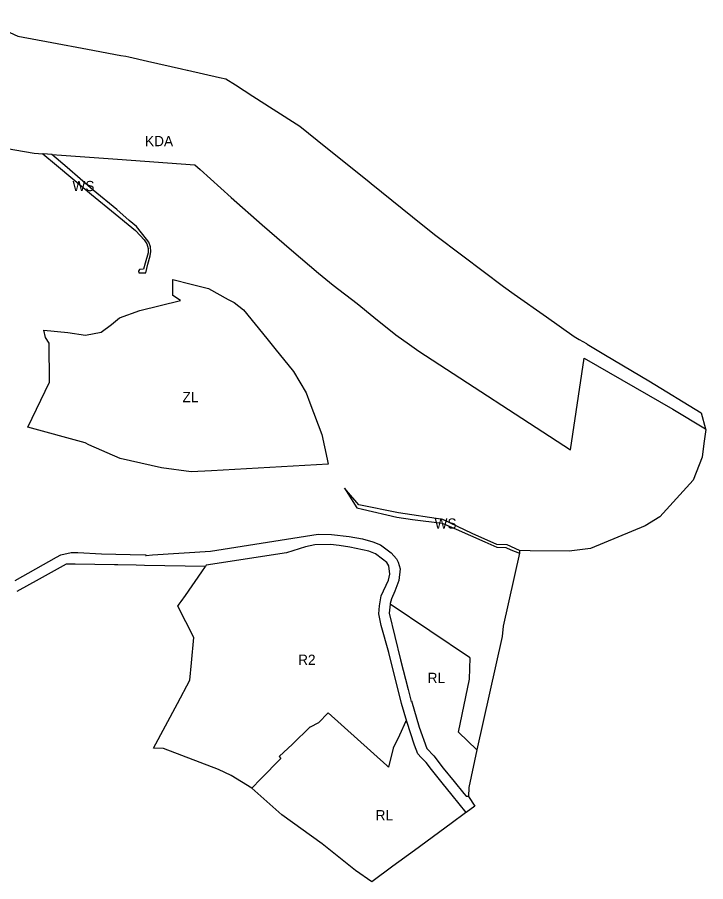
# Model space of a CAD drawing. Extents: x 7413438 to 7416393, y 5541665 to 5544118.
# Drawn here: x 7415988 to 7416393, y 5542838 to 5543346 of the extents above; entities that cross this region are included whole.
import ezdxf

# ---------------------------------------------------------------- set-up
doc = ezdxf.new("R2010")
doc.units = 0
doc.layers.add('linie_rozgraniczajace', color=7, linetype='Continuous')
doc.layers.add('oznaczenia_przeznaczen', color=7, linetype='Continuous')

msp = doc.modelspace()

# ---------------------------------------------------------------- linework, layer by layer
at = {"layer": 'linie_rozgraniczajace'}
for p, q in [((7415964.26, 5543346), (7415988.61, 5543334.9)), ((7415988.61, 5543334.9), (7416008.67, 5543331.16)), ((7416008.67, 5543331.16), (7416029.55, 5543327.27)), ((7416029.55, 5543327.27), (7416049.05, 5543323.64)), ((7416049.05, 5543323.64), (7416052.1, 5543323.07)), ((7416052.1, 5543323.07), (7416053.82, 5543322.68)), ((7416053.82, 5543322.68), (7416064.8, 5543320.22)), ((7416064.8, 5543320.22), (7416084.77, 5543315.73)), ((7416084.77, 5543315.73), (7416088.21, 5543314.96)), ((7416088.21, 5543314.96), (7416088.33, 5543314.93)), ((7416088.33, 5543314.93), (7416107.21, 5543310.69)), ((7416107.21, 5543310.69), (7416110.82, 5543309.87)), ((7416110.82, 5543309.87), (7416116.51, 5543306.22)), ((7416116.51, 5543306.22), (7416126.74, 5543299.66)), ((7416126.74, 5543299.66), (7416138.7, 5543291.99)), ((7416138.7, 5543291.99), (7416154.38, 5543281.93)), ((7416154.38, 5543281.93), (7416169.6, 5543269.75)), ((7415958.11, 5543273.01), (7415998.1, 5543266.23)), ((7415998.1, 5543266.23), (7416003.27, 5543265.76)), ((7416003.27, 5543265.76), (7416011.26, 5543259.11)), ((7416003.53, 5543265.74), (7416003.27, 5543265.76)), ((7416008.6, 5543265.34), (7416003.53, 5543265.74)), ((7416008.6, 5543265.34), (7416014.24, 5543264.89)), ((7416017.58, 5543257.77), (7416008.6, 5543265.34)), ((7416014.24, 5543264.89), (7416047.21, 5543262.67)), ((7416169.6, 5543269.75), (7416194.01, 5543250.2)), ((7416047.21, 5543262.67), (7416092.62, 5543259.25)), ((7416011.26, 5543259.11), (7416020.83, 5543251.16)), ((7416032.85, 5543244.48), (7416017.58, 5543257.77)), ((7416092.62, 5543259.25), (7416095.86, 5543256.53)), ((7416095.86, 5543256.53), (7416114.03, 5543240.05)), ((7416020.83, 5543251.16), (7416031.97, 5543241.8)), ((7416194.01, 5543250.2), (7416196.24, 5543248.41)), ((7416196.24, 5543248.41), (7416220.56, 5543228.8)), ((7416031.97, 5543241.8), (7416045.82, 5543230.57)), ((7416046.75, 5543233.11), (7416032.85, 5543244.48)), ((7416114.03, 5543240.05), (7416132.19, 5543223.99)), ((7416045.82, 5543230.57), (7416055.66, 5543222.46)), ((7416054.06, 5543226.67), (7416046.75, 5543233.11)), ((7416058.31, 5543223.08), (7416054.06, 5543226.67)), ((7416220.56, 5543228.8), (7416233.46, 5543218.41)), ((7416055.66, 5543222.46), (7416057.67, 5543220.64)), ((7416057.67, 5543220.64), (7416060.43, 5543217.77)), ((7416064.15, 5543215.54), (7416058.31, 5543223.08)), ((7416132.19, 5543223.99), (7416149.45, 5543209.17)), ((7416060.43, 5543217.77), (7416062.78, 5543215.14)), ((7416062.78, 5543215.14), (7416064.38, 5543212.96)), ((7416065.51, 5543213.87), (7416064.15, 5543215.54)), ((7416233.46, 5543218.41), (7416250.23, 5543205.76)), ((7416064.38, 5543212.96), (7416065.23, 5543210.14)), ((7416065.23, 5543210.14), (7416065.16, 5543207.67)), ((7416066.66, 5543211.1), (7416065.51, 5543213.87)), ((7416066.73, 5543208.38), (7416066.66, 5543211.1)), ((7416149.45, 5543209.17), (7416165.37, 5543195.73)), ((7416065.16, 5543207.67), (7416063.37, 5543201.55)), ((7416064.91, 5543201.01), (7416066.31, 5543205.82)), ((7416066.31, 5543205.82), (7416066.73, 5543208.38)), ((7416250.23, 5543205.76), (7416274.14, 5543187.71)), ((7416063.37, 5543201.55), (7416062.47, 5543197.96)), ((7416063.74, 5543195.84), (7416064.91, 5543201.01)), ((7416060.12, 5543197.87), (7416059.58, 5543196.76)), ((7416059.58, 5543196.76), (7416059.75, 5543195.91)), ((7416059.75, 5543195.91), (7416063.74, 5543195.84)), ((7416062.47, 5543197.96), (7416060.12, 5543197.87)), ((7416165.37, 5543195.73), (7416173.92, 5543188.53)), ((7416079.65, 5543182.59), (7416079.61, 5543191.89)), ((7416079.61, 5543191.89), (7416090.46, 5543189.16)), ((7416090.46, 5543189.16), (7416100.7, 5543186.6)), ((7416100.7, 5543186.6), (7416112.31, 5543180.21)), ((7416173.92, 5543188.53), (7416188.02, 5543177.72)), ((7416274.14, 5543187.71), (7416280.35, 5543183.33)), ((7416060.21, 5543173.64), (7416084.18, 5543179.62)), ((7416084.18, 5543179.62), (7416079.65, 5543182.59)), ((7416112.31, 5543180.21), (7416115.74, 5543178.32)), ((7416280.35, 5543183.33), (7416299.31, 5543169.98)), ((7416048.42, 5543169.44), (7416060.21, 5543173.64)), ((7416115.74, 5543178.32), (7416121.24, 5543174.19)), ((7416121.24, 5543174.19), (7416134.9, 5543157.31)), ((7416188.02, 5543177.72), (7416197.88, 5543169.72)), ((7416043.64, 5543165.38), (7416048.42, 5543169.44)), ((7416197.88, 5543169.72), (7416210.82, 5543159.43)), ((7416299.31, 5543169.98), (7416315.66, 5543158.46)), ((7416037.64, 5543160.91), (7416043.64, 5543165.38)), ((7416004.9, 5543157.83), (7416003.95, 5543162.06)), ((7416003.95, 5543162.06), (7416018.07, 5543160.8)), ((7416018.07, 5543160.8), (7416028.33, 5543159.29)), ((7416028.33, 5543159.29), (7416037.64, 5543160.91)), ((7416210.82, 5543159.43), (7416218.75, 5543153.63)), ((7416315.66, 5543158.46), (7416318.55, 5543156.74)), ((7416007.07, 5543154.49), (7416004.9, 5543157.83)), ((7416007.2, 5543131.63), (7416007.07, 5543154.49)), ((7416134.9, 5543157.31), (7416139.71, 5543151.36)), ((7416218.75, 5543153.63), (7416224.31, 5543149.72)), ((7416318.55, 5543156.74), (7416322.76, 5543154.23)), ((7416322.76, 5543154.23), (7416323.21, 5543153.96)), ((7416323.21, 5543153.96), (7416334.03, 5543147.49)), ((7416139.71, 5543151.36), (7416150.57, 5543137.93)), ((7416224.31, 5543149.72), (7416313.49, 5543091.85)), ((7416313.49, 5543091.85), (7416321.55, 5543145.7)), ((7416321.55, 5543145.7), (7416373.58, 5543115.7)), ((7416334.03, 5543147.49), (7416359.44, 5543132.32)), ((7416150.57, 5543137.93), (7416157.98, 5543125.35)), ((7415994.55, 5543105.07), (7416007.2, 5543131.63)), ((7416359.44, 5543132.32), (7416390.16, 5543113.61)), ((7416157.98, 5543125.35), (7416160.18, 5543119.5)), ((7416160.18, 5543119.5), (7416167.19, 5543100.83)), ((7416373.58, 5543115.7), (7416392.82, 5543104.09)), ((7416390.16, 5543113.61), (7416392.82, 5543104.09)), ((7416028.1, 5543095.85), (7415994.55, 5543105.07)), ((7416392.9, 5543103.82), (7416391.85, 5543095.5)), ((7416392.82, 5543104.09), (7416392.9, 5543103.82)), ((7416167.19, 5543100.83), (7416170.37, 5543086.25)), ((7416030.39, 5543094.83), (7416028.1, 5543095.85)), ((7416048.66, 5543086.72), (7416030.39, 5543094.83)), ((7416391.85, 5543095.5), (7416390.84, 5543087.45)), ((7416391.85, 5543095.5), (7416391.85, 5543095.5)), ((7416390.84, 5543087.45), (7416385.47, 5543073.91)), ((7416073.06, 5543081.27), (7416048.66, 5543086.72)), ((7416170.99, 5543083.32), (7416102.34, 5543079.47)), ((7416170.37, 5543086.25), (7416170.99, 5543083.32)), ((7416090.4, 5543078.81), (7416073.06, 5543081.27)), ((7416102.34, 5543079.47), (7416090.4, 5543078.81)), ((7416385.47, 5543073.91), (7416365.99, 5543052.55)), ((7416189.02, 5543059.53), (7416180.6, 5543069.36)), ((7416180.6, 5543069.36), (7416187.89, 5543057.81)), ((7416187.89, 5543057.81), (7416191.2, 5543057.01)), ((7416212.3, 5543054.85), (7416189.02, 5543059.53)), ((7416191.2, 5543057.01), (7416211.33, 5543052.34)), ((7416211.33, 5543052.34), (7416220.55, 5543050.97)), ((7416238.42, 5543050.83), (7416212.3, 5543054.85)), ((7416365.99, 5543052.55), (7416357.3, 5543047.16)), ((7416220.55, 5543050.97), (7416238.04, 5543048.81)), ((7416238.04, 5543048.81), (7416246.14, 5543045.19)), ((7416255.62, 5543042.63), (7416238.42, 5543050.83)), ((7416357.3, 5543047.16), (7416325.24, 5543033.84)), ((7416101.84, 5543032.35), (7416165.08, 5543042.24)), ((7416165.08, 5543042.24), (7416172.95, 5543042.1)), ((7416172.95, 5543042.1), (7416183.33, 5543040.89)), ((7416246.14, 5543045.19), (7416262.98, 5543037.71)), ((7416270.06, 5543036.19), (7416255.62, 5543042.63)), ((7416183.33, 5543040.89), (7416191.18, 5543039.44)), ((7416191.18, 5543039.44), (7416197.24, 5543037.7)), ((7416197.24, 5543037.7), (7416201.74, 5543036.04)), ((7416262.98, 5543037.71), (7416270.19, 5543034.66)), ((7416013.81, 5543030.15), (7416019.99, 5543031.53)), ((7416019.99, 5543031.53), (7416023.91, 5543031.45)), ((7416023.91, 5543031.45), (7416037.78, 5543030.79)), ((7416067.72, 5543030.04), (7416101.8, 5543032.34)), ((7416146.52, 5543031.29), (7416099.2, 5543023.98)), ((7416101.8, 5543032.34), (7416101.84, 5543032.34)), ((7416101.84, 5543032.34), (7416101.84, 5543032.35)), ((7416157.7, 5543034.78), (7416146.52, 5543031.29)), ((7416163.25, 5543036.01), (7416157.7, 5543034.78)), ((7416172.39, 5543036.12), (7416163.25, 5543036.01)), ((7416177.47, 5543035.53), (7416172.39, 5543036.12)), ((7416183.81, 5543034.7), (7416177.47, 5543035.53)), ((7416194.81, 5543032.2), (7416183.81, 5543034.7)), ((7416198.73, 5543030.81), (7416194.81, 5543032.2)), ((7416201.74, 5543036.04), (7416207.97, 5543031.27)), ((7416207.97, 5543031.27), (7416211.08, 5543027.84)), ((7416276.22, 5543036.04), (7416270.06, 5543036.19)), ((7416270.19, 5543034.66), (7416275.42, 5543034.47)), ((7416275.42, 5543034.47), (7416278.42, 5543033.05)), ((7416283.54, 5543032.6), (7416276.22, 5543036.04)), ((7416278.42, 5543033.05), (7416283.36, 5543031.15)), ((7416283.41, 5543032.61), (7416283.36, 5543031.15)), ((7416283.54, 5543032.6), (7416283.41, 5543032.61)), ((7416289.72, 5543032.52), (7416283.54, 5543032.6)), ((7416312.67, 5543032.21), (7416289.72, 5543032.52)), ((7416325.24, 5543033.84), (7416312.67, 5543032.21)), ((7415986.94, 5543015.08), (7416011.39, 5543028.84)), ((7416011.39, 5543028.84), (7416013.81, 5543030.15)), ((7416037.78, 5543030.79), (7416054.7, 5543030.34)), ((7416054.7, 5543030.34), (7416063.67, 5543030.22)), ((7416063.67, 5543030.22), (7416063.77, 5543030.13)), ((7416063.77, 5543030.13), (7416063.73, 5543029.78)), ((7416063.73, 5543029.78), (7416063.99, 5543029.79)), ((7416063.99, 5543029.79), (7416067.72, 5543030.04)), ((7416202.98, 5543027.54), (7416198.73, 5543030.81)), ((7416205.39, 5543025.68), (7416202.98, 5543027.54)), ((7416211.08, 5543027.84), (7416212.2, 5543025.74)), ((7416283.36, 5543031.12), (7416273.83, 5542988.21)), ((7416283.36, 5543031.15), (7416283.36, 5543031.12)), ((7416016.95, 5543024.73), (7416001.1, 5543015.87)), ((7416022.19, 5543024.64), (7416016.95, 5543024.73)), ((7416022.26, 5543024.63), (7416022.19, 5543024.64)), ((7416045.42, 5543024.2), (7416022.26, 5543024.63)), ((7416047.33, 5543024.16), (7416045.42, 5543024.2)), ((7416058.15, 5543023.96), (7416047.33, 5543024.16)), ((7416063.04, 5543023.87), (7416058.15, 5543023.96)), ((7416063.07, 5543023.86), (7416063.04, 5543023.87)), ((7416098.95, 5543023.19), (7416063.07, 5543023.86)), ((7416096.82, 5543020.16), (7416098.95, 5543023.19)), ((7416099.2, 5543023.98), (7416098.95, 5543023.19)), ((7416206.56, 5543023.66), (7416205.39, 5543025.68)), ((7416207.25, 5543018.8), (7416206.56, 5543023.66)), ((7416212.2, 5543025.74), (7416213.25, 5543021.86)), ((7416213.25, 5543021.86), (7416212.51, 5543015.07)), ((7416087.05, 5543006.28), (7416096.82, 5543020.16)), ((7416206.37, 5543015.24), (7416207.25, 5543018.8)), ((7416001.1, 5543015.87), (7415987.94, 5543008.51)), ((7416202.24, 5543005.95), (7416206.37, 5543015.24)), ((7416212.51, 5543015.07), (7416210.2, 5543008.74)), ((7416084.56, 5543002.73), (7416087.05, 5543006.28)), ((7416201.17, 5543000.17), (7416202.24, 5543005.95)), ((7416210.2, 5543008.74), (7416208.12, 5543004.33)), ((7416082.66, 5543000.03), (7416083.43, 5543001.12)), ((7416083.43, 5543001.12), (7416084.56, 5543002.73)), ((7416207.51, 5543001.1), (7416206.81, 5542995.83)), ((7416207.49, 5543001.54), (7416207.44, 5543001.14)), ((7416207.44, 5543001.14), (7416207.51, 5543001.1)), ((7416208.12, 5543004.33), (7416207.49, 5543001.54)), ((7416254.1, 5542969.87), (7416207.51, 5543001.1)), ((7416091.97, 5542981.46), (7416082.66, 5543000.03)), ((7416200.77, 5542995.43), (7416201.17, 5543000.17)), ((7416206.81, 5542995.83), (7416213.57, 5542968.44)), ((7416202.2, 5542988.61), (7416200.77, 5542995.43)), ((7416206.59, 5542972.7), (7416202.2, 5542988.61)), ((7416273.83, 5542988.21), (7416273.19, 5542982.19)), ((7416090.61, 5542966.74), (7416091.97, 5542981.46)), ((7416273.19, 5542982.19), (7416258.46, 5542915.55)), ((7416214.09, 5542942.84), (7416206.59, 5542972.7)), ((7416089.66, 5542956.4), (7416090.61, 5542966.74)), ((7416213.57, 5542968.44), (7416218.01, 5542950.98)), ((7416253.99, 5542956.98), (7416254.54, 5542969.58)), ((7416254.54, 5542969.58), (7416254.1, 5542969.87)), ((7416082.35, 5542942.72), (7416089.66, 5542956.4)), ((7416247.57, 5542926), (7416253.99, 5542956.98)), ((7416218.01, 5542950.98), (7416219.78, 5542943.95)), ((7416068.33, 5542916.52), (7416082.35, 5542942.72)), ((7416217.25, 5542932.13), (7416214.09, 5542942.84)), ((7416219.78, 5542943.95), (7416219.9, 5542944.34)), ((7416219.9, 5542944.34), (7416224.48, 5542928.84)), ((7416170.94, 5542937.32), (7416165.33, 5542931.38)), ((7416205.45, 5542906.24), (7416170.94, 5542937.32)), ((7416165.3, 5542931.4), (7416160.37, 5542928.88)), ((7416165.33, 5542931.38), (7416165.3, 5542931.4)), ((7416216.71, 5542932.4), (7416212.96, 5542924.07)), ((7416216.93, 5542931.58), (7416216.71, 5542932.4)), ((7416217.25, 5542932.13), (7416216.93, 5542931.58)), ((7416221.68, 5542918.32), (7416217.25, 5542932.13)), ((7416157.78, 5542926.48), (7416152.52, 5542921.35)), ((7416160.31, 5542928.92), (7416157.78, 5542926.48)), ((7416160.37, 5542928.88), (7416160.31, 5542928.92)), ((7416224.48, 5542928.84), (7416228.95, 5542916.24)), ((7416258.46, 5542915.55), (7416247.57, 5542926)), ((7416152.52, 5542921.35), (7416149.95, 5542918.92)), ((7416212.96, 5542924.07), (7416209.29, 5542916.5)), ((7416074.22, 5542916.33), (7416068.33, 5542916.52)), ((7416106.58, 5542904), (7416074.22, 5542916.33)), ((7416149.95, 5542918.92), (7416142.14, 5542911.53)), ((7416209.29, 5542916.5), (7416206.52, 5542905.27)), ((7416223.75, 5542913.13), (7416221.68, 5542918.32)), ((7416228.95, 5542916.24), (7416233.19, 5542911.93)), ((7416258.46, 5542915.55), (7416253.59, 5542893.49)), ((7416143.09, 5542910.4), (7416131.51, 5542898.54)), ((7416142.14, 5542911.53), (7416143.09, 5542910.4)), ((7416225.72, 5542910.98), (7416223.75, 5542913.13)), ((7416228.53, 5542908.14), (7416225.72, 5542910.98)), ((7416233.19, 5542911.93), (7416238.66, 5542904.74)), ((7416206.52, 5542905.27), (7416205.45, 5542906.24)), ((7416231.68, 5542904.01), (7416228.53, 5542908.14)), ((7416238.66, 5542904.74), (7416245.08, 5542896.97)), ((7416114.02, 5542900.41), (7416106.58, 5542904)), ((7416126.09, 5542892.99), (7416114.02, 5542900.41)), ((7416237.99, 5542896.13), (7416231.68, 5542904.01)), ((7416131.51, 5542898.54), (7416126.09, 5542892.99)), ((7416243.82, 5542888.87), (7416237.99, 5542896.13)), ((7416245.08, 5542896.97), (7416250.77, 5542889.88)), ((7416143.8, 5542877.44), (7416126.09, 5542892.99)), ((7416250.77, 5542889.88), (7416252.01, 5542888.33)), ((7416253.59, 5542893.49), (7416253.4, 5542888.21)), ((7416252.03, 5542878.67), (7416243.82, 5542888.87)), ((7416252.01, 5542888.33), (7416253.36, 5542888.22)), ((7416253.36, 5542888.22), (7416253.4, 5542888.21)), ((7416253.4, 5542888.21), (7416253.39, 5542888.14)), ((7416253.39, 5542888.14), (7416257.26, 5542882.51)), ((7416257.26, 5542882.51), (7416252.03, 5542878.67)), ((7416167.52, 5542860.29), (7416143.8, 5542877.44)), ((7416251.76, 5542878.47), (7416243.29, 5542872.25)), ((7416252.03, 5542878.67), (7416251.76, 5542878.47)), ((7416243.29, 5542872.25), (7416221.68, 5542856.4)), ((7416187, 5542844.56), (7416167.52, 5542860.29)), ((7416221.68, 5542856.4), (7416209, 5542847.1)), ((7416196.66, 5542838.05), (7416187, 5542844.56)), ((7416209, 5542847.1), (7416196.66, 5542838.05))]:
    msp.add_line(p, q, dxfattribs=at)

# ---------------------------------------------------------------- texts
at = {"layer": 'oznaczenia_przeznaczen'}
for s, p in [('KDA', (7416063.35, 5543270.25)), ('WS', (7416020.71, 5543243.85)), ('ZL', (7416085.36, 5543119.82)), ('WS', (7416233.54, 5543045.5)), ('R2', (7416153.33, 5542965.48)), ('RL', (7416229.45, 5542954.82)), ('RL', (7416198.88, 5542874.13))]:
    msp.add_text(s, height=6, dxfattribs=at).set_placement(p)

doc.saveas('drawing.dxf')
